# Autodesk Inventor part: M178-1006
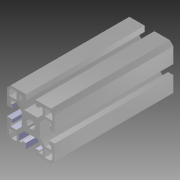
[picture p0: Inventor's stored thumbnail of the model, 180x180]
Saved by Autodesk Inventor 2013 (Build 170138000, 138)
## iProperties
Created: 2004-10
Material: Aluminium - 6061
Document SubType Name: Modeling
Designer: Autodesk, Inc.
Manufacturer: Standard
Standards Organization: Custom
Description: TABLE, SUPPORT CROSS BAR
Stock Number: 10-040
Catalog Web Link: http://www.parker.com/ead/cm1.asp?cmid=809
Vendor: PARKER IPS
Part Number: M178-1006
Mass: 179.948 g
Surface Area: 483.565 cm^2
Volume: 66.4013 cm^3
Density: 2.71 g/cm^3
CAGE: 1LJX3
Dept. ID: Product Design
Description #2: ---
Finish #1: ---
Finish #2: ---
Material ID: ---
Project Number: ---
Length: 1748.800 mm
Author: Autodesk, Inc.
Revision Number: A
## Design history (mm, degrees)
derived "40 Series Profiles.ipt"
feature "IPS40SeriesCutout1"
mirror "Mirror1"
body "Solid1"
tag "TaggingFeature2"
sketch "Sketch1"
  geometry: L1 (20, 824.4)-(-1, 824.4) reference; L2 (-1, -924.4)-(-1, 824.4) reference; L3 (7, 824.4)-(7, -924.4) reference; L4 (-1, 804.4)-(7, 804.4); C1 r 10 at (3, 804.4)
  constraints: 2 end point, 2 point on line, 1 centre point, 1 midpoint, 1 perpendicular
  dimensions: "d0" = 20 distance between parallel lines of L4 L1; "d1" = 20 diameter of C1
feature "Solid1::40 Series Profiles.ipt" dims "ScaleForDerivedMember" = 10
other parameters: "Length" = 1748.8
